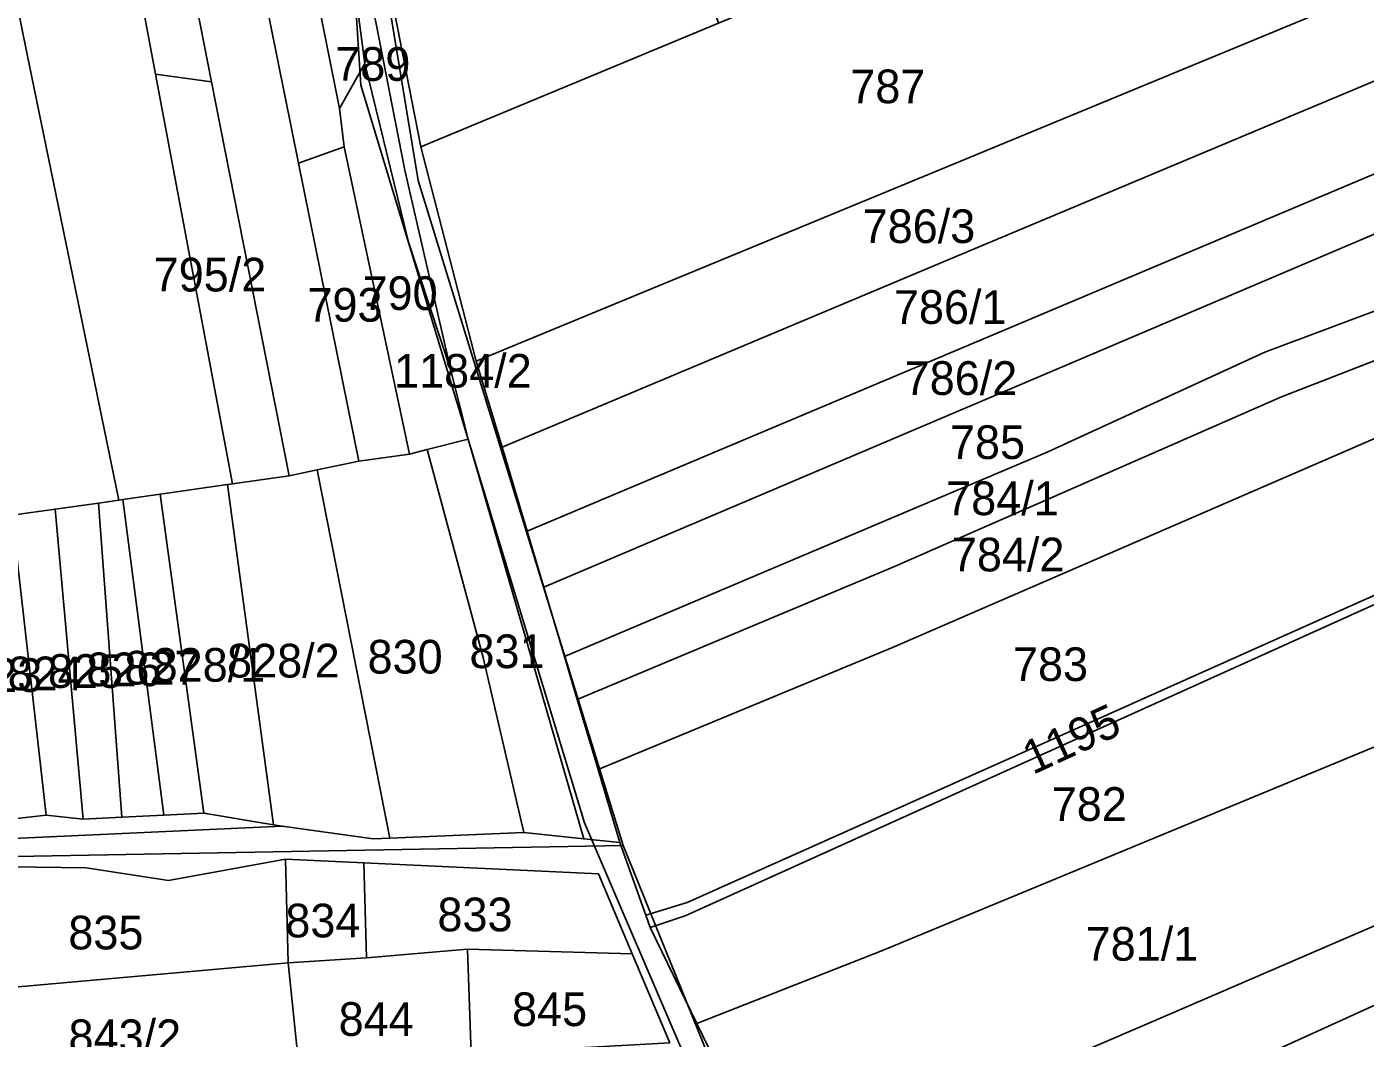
# Model space of a CAD drawing. Extents: x -623250 to -619626, y -1079612 to -1075424.
# Drawn here: x -621038.1 to -620640.4, y -1077296.6 to -1076996.3 of the extents above; entities that cross this region are included whole.
import ezdxf

# ---------------------------------------------------------------- set-up
doc = ezdxf.new("R2010")
doc.units = 0
for name, color, linetype in [('Cestní síť', 7, 'Continuous'), ('Parcela nároku', 7, 'Continuous'), ('Parcelní číslo', 7, 'Continuous'), ('Vodní toky', 7, 'Continuous')]:
    doc.layers.add(name, color=color, linetype=linetype)

msp = doc.modelspace()

# ---------------------------------------------------------------- linework, layer by layer
at = {"layer": 'Cestní síť'}
for p, q in [((-620921.78, -1077041.94), (-620941.41, -1076923.5)), ((-620860.93, -1077239.33), (-620921.78, -1077041.94)), ((-620860.93, -1077239.33), (-621214.45, -1077245.82)), ((-620817.17, -1077347.1), (-620860.93, -1077239.33))]:
    msp.add_line(p, q, dxfattribs=at)
at = {"layer": 'Parcela nároku'}
for points in [[(-620972.42, -1076884.35), (-620988.51, -1076803.88), (-621002.65, -1076813.04), (-620979.97, -1076924.9), (-620957.34, -1077036.71), (-620943.82, -1077031.86), (-620945.19, -1077020.56)], [(-620939.41, -1077125.24), (-620957.34, -1077036.71), (-620979.97, -1076924.9), (-621002.65, -1076813.04), (-621020.06, -1076825.27), (-620983.2, -1077012.58), (-620960.16, -1077129.62), (-620951.82, -1077127.86)], [(-621032.81, -1076834.22), (-621020.06, -1076825.27), (-620983.2, -1077012.58), (-620999.81, -1077010.33)], [(-621040.87, -1076839.88), (-621032.81, -1076834.22), (-620999.81, -1077010.33), (-620977.01, -1077132.01), (-620978.48, -1077132.22), (-620998.5, -1077135.06), (-621009.6, -1077136.64), (-621010.77, -1077136.81), (-621038.05, -1077003.98), (-621065.15, -1076871.1)], [(-621065.15, -1076871.1), (-621038.05, -1077003.98), (-621010.77, -1077136.81), (-621016.81, -1077137.67), (-621029.67, -1077139.5), (-621042.47, -1077141.32), (-621054.91, -1077143.09), (-621078.91, -1077021.62), (-621102.95, -1076900.09), (-621076.1, -1076880.89)], [(-620945.17, -1076884.69), (-620944.66, -1076880.6), (-620940.19, -1076870.41), (-620938.3, -1076883.42), (-620943.44, -1076948.79), (-620925.77, -1077038.84), (-620912.07, -1077098.28), (-620924.65, -1077060.22), (-620937.66, -1077007.21), (-620944.07, -1076958.4), (-620947.15, -1076948.49), (-620946.76, -1076928.27), (-620947.86, -1076911.3)], [(-620951.9, -1076932.96), (-620947.15, -1076948.49), (-620944.07, -1076958.4), (-620937.66, -1077007.21), (-620945.19, -1077020.56), (-620972.42, -1076884.35), (-620950.76, -1076884.62), (-620953.69, -1076914.5)], [(-620860.19, -1076914.89), (-620832.54, -1076995.23), (-620921.02, -1077031.86), (-620937.66, -1076946.83), (-620887.44, -1076925.53)], [(-620629.28, -1076981.86), (-620643.85, -1076916.74), (-620738.29, -1076956.01), (-620832.54, -1076995.23), (-620921.02, -1077031.86), (-620904.58, -1077095.56), (-620767.08, -1077038.8)], [(-620767.08, -1077038.8), (-620904.58, -1077095.56), (-620896.8, -1077121.07), (-620760.56, -1077063.88), (-620624.13, -1077006.64), (-620629.28, -1076981.86)], [(-620999.81, -1077010.33), (-620983.2, -1077012.58), (-620960.16, -1077129.62), (-620977.01, -1077132.01)], [(-620912.07, -1077098.28), (-620924.65, -1077060.22), (-620937.66, -1077007.21), (-620945.19, -1077020.56), (-620943.82, -1077031.86), (-620924.38, -1077123.14), (-620919.18, -1077121.81), (-620906.95, -1077118.69)], [(-620618.82, -1077032.03), (-620624.13, -1077006.64), (-620760.56, -1077063.88), (-620896.8, -1077121.07), (-620889.38, -1077146.03), (-620754.08, -1077089.06)], [(-620943.82, -1077031.86), (-620957.34, -1077036.71), (-620939.41, -1077125.24), (-620924.38, -1077123.14)], [(-620754.08, -1077089.06), (-620618.82, -1077032.03), (-620615.34, -1077048.34), (-620749.99, -1077105.51), (-620884.45, -1077162.62), (-620889.38, -1077146.03)], [(-620749.99, -1077105.51), (-620615.34, -1077048.34), (-620610.74, -1077070.63), (-620670.29, -1077092.89), (-620734.88, -1077122.56), (-620878.33, -1077183.21), (-620884.45, -1077162.62)], [(-620670.29, -1077092.89), (-620734.88, -1077122.56), (-620878.33, -1077183.21), (-620874.52, -1077196.05), (-620780.25, -1077156.48), (-620665.33, -1077106.16), (-620607.96, -1077083.92), (-620610.74, -1077070.63)], [(-620665.33, -1077106.16), (-620607.96, -1077083.92), (-620603.79, -1077103.85), (-620780.87, -1077180.56), (-620868.37, -1077216.75), (-620874.52, -1077196.05), (-620780.25, -1077156.48)], [(-620603.79, -1077103.85), (-620780.87, -1077180.56), (-620868.37, -1077216.75), (-620861.9, -1077238.51), (-620854.18, -1077260.06), (-620841.88, -1077256.29), (-620720.81, -1077202.26), (-620599.73, -1077148.14)], [(-620906.95, -1077118.69), (-620872.61, -1077237.42), (-620890.39, -1077235.55), (-620902.5, -1077183.58), (-620919.18, -1077121.81)], [(-620951.82, -1077127.86), (-620939.41, -1077125.24), (-620924.38, -1077123.14), (-620919.18, -1077121.81), (-620902.5, -1077183.58), (-620890.39, -1077235.55), (-620930.21, -1077237.15)], [(-620978.48, -1077132.22), (-620977.01, -1077132.01), (-620960.16, -1077129.62), (-620951.82, -1077127.86), (-620930.21, -1077237.15), (-620935.21, -1077237.35), (-620962.22, -1077233.64), (-620964.79, -1077233.21)], [(-620978.48, -1077132.22), (-620964.79, -1077233.21), (-620985.48, -1077229.75), (-620998.5, -1077135.06)], [(-621016.81, -1077137.67), (-621010.77, -1077136.81), (-621009.6, -1077136.64), (-620997.36, -1077230.34), (-621009.82, -1077230.96)], [(-621009.6, -1077136.64), (-620998.5, -1077135.06), (-620985.48, -1077229.75), (-620997.36, -1077230.34)], [(-621032.37, -1077230.4), (-621042.47, -1077141.32), (-621054.91, -1077143.09), (-621044.66, -1077231.77)], [(-621021.32, -1077231.53), (-621029.67, -1077139.5), (-621042.47, -1077141.32), (-621032.37, -1077230.4)], [(-621029.67, -1077139.5), (-621016.81, -1077137.67), (-621009.82, -1077230.96), (-621021.32, -1077231.53)], [(-620854.18, -1077260.06), (-620841.88, -1077256.29), (-620720.81, -1077202.26), (-620599.73, -1077148.14), (-620597.96, -1077153.14), (-620616.17, -1077158.13), (-620729.34, -1077209.18), (-620842.44, -1077260.29), (-620852.88, -1077263.68)], [(-620729.34, -1077209.18), (-620842.44, -1077260.29), (-620852.88, -1077263.68), (-620839.03, -1077292.21), (-620783.8, -1077270.52), (-620686.15, -1077230.15), (-620588.31, -1077189.72), (-620593.55, -1077165.29), (-620597.96, -1077153.14), (-620616.17, -1077158.13)], [(-620686.15, -1077230.15), (-620783.8, -1077270.52), (-620839.03, -1077292.21), (-620824.5, -1077322.12), (-620818.03, -1077340.86), (-620698.27, -1077289.33), (-620578.2, -1077237.62), (-620588.31, -1077189.72)], [(-621166.67, -1077233.21), (-621156.36, -1077231.82), (-621144.12, -1077230.17), (-621129.77, -1077230.27), (-621116.92, -1077228.86), (-621105.4, -1077230.88), (-621067.47, -1077233.41), (-621055.85, -1077230.4), (-621044.66, -1077231.77), (-621032.37, -1077230.4), (-621021.32, -1077231.53), (-621009.82, -1077230.96), (-620997.36, -1077230.34), (-620985.48, -1077229.75), (-620964.79, -1077233.21), (-620962.22, -1077233.64), (-621085.4, -1077239.27), (-621216.53, -1077243.73), (-621220.15, -1077236.58), (-621210.93, -1077235.6), (-621181.64, -1077232.5)], [(-620698.27, -1077289.33), (-620578.2, -1077237.62), (-620573.82, -1077257.79), (-620688.76, -1077310.04), (-620812.33, -1077364.99), (-620818.03, -1077340.86)], [(-620995.94, -1077249.72), (-621020.46, -1077245.96), (-621072.57, -1077245.28), (-621061.68, -1077274.39), (-621059.63, -1077283.02), (-620960.48, -1077274.17), (-620961.21, -1077243.43)], [(-620937.95, -1077244.51), (-620937.13, -1077272.7), (-620960.48, -1077274.17), (-620961.21, -1077243.43)], [(-620858.19, -1077271.52), (-620868.27, -1077247.75), (-620937.95, -1077244.51), (-620937.13, -1077272.7), (-620907.16, -1077270.11)], [(-620564.8, -1077306.77), (-620573.82, -1077257.79), (-620688.76, -1077310.04), (-620812.33, -1077364.99), (-620813.72, -1077378.79), (-620674.53, -1077339)], [(-620937.13, -1077272.7), (-620907.16, -1077270.11), (-620906.02, -1077301.21), (-620957.12, -1077305.77), (-620960.48, -1077274.17)], [(-620846.99, -1077297.92), (-620858.19, -1077271.52), (-620907.16, -1077270.11), (-620906.02, -1077301.21)], [(-620960.48, -1077274.17), (-620957.12, -1077305.77), (-620974.2, -1077305.88), (-620976.64, -1077305.9), (-621034.08, -1077311.92), (-621045.83, -1077293.38), (-621058.93, -1077294.62), (-621059.63, -1077283.02)]]:
    msp.add_lwpolyline(points, close=True, dxfattribs=at)
for points in [[(-620937.66, -1076946.83), (-620921.02, -1077031.86), (-620904.58, -1077095.56), (-620896.8, -1077121.07), (-620889.38, -1077146.03), (-620884.45, -1077162.62), (-620878.33, -1077183.21), (-620874.52, -1077196.05), (-620868.37, -1077216.75), (-620861.9, -1077238.51), (-620872.61, -1077237.42), (-620906.95, -1077118.69), (-620912.07, -1077098.28), (-620925.77, -1077038.84), (-620943.44, -1076948.79)], [(-621085.4, -1077239.27), (-620962.22, -1077233.64), (-620935.21, -1077237.35), (-620930.21, -1077237.15), (-620890.39, -1077235.55), (-620872.61, -1077237.42), (-620861.9, -1077238.51), (-620854.18, -1077260.06), (-620852.88, -1077263.68), (-620839.03, -1077292.21), (-620824.5, -1077322.12)], [(-620846.99, -1077297.92), (-620858.19, -1077271.52), (-620868.27, -1077247.75), (-620937.95, -1077244.51), (-620961.21, -1077243.43), (-620995.94, -1077249.72), (-621020.46, -1077245.96), (-621072.57, -1077245.28)]]:
    msp.add_lwpolyline(points, dxfattribs=at)
at = {"layer": 'Vodní toky'}
for p, q in [((-620938.8, -1077013.58), (-620945.97, -1076901.34)), ((-620903.15, -1077131.23), (-620938.8, -1077013.58)), ((-620872.43, -1077232.6), (-620903.15, -1077131.23)), ((-620826.67, -1077339.21), (-620872.43, -1077232.6))]:
    msp.add_line(p, q, dxfattribs=at)

# ---------------------------------------------------------------- texts
at = {"layer": 'Parcelní číslo'}
for s, p in [('789', (-620946.44, -1077012.31)), ('787', (-620793.41, -1077018.96)), ('786/3', (-620789.75, -1077060.48)), ('795/2', (-621000.4, -1077074.85)), ('793', (-620954.71, -1077083.82)), ('790', (-620938.33, -1077080.35)), ('786/1', (-620780.47, -1077084.47)), ('1184/2', (-620928.97, -1077103.42)), ('786/2', (-620777.26, -1077105.57)), ('785', (-620763.81, -1077124.6)), ('784/1', (-620764.94, -1077141.28)), ('784/2', (-620763.24, -1077157.97)), ('831', (-620906.57, -1077186.7)), ('828/1', (-621000.71, -1077190.73)), ('828/2', (-620978.58, -1077189.48)), ('830', (-620936.85, -1077188.31)), ('783', (-620745.09, -1077190.53)), ('823', (-621055.79, -1077193.76)), ('824', (-621043.77, -1077193.27)), ('825', (-621031.78, -1077192.56)), ('826', (-621020.38, -1077192.06)), ('827', (-621009.09, -1077191.56)), ('782', (-620733.56, -1077232.05)), ('834', (-620961.27, -1077266.65)), ('833', (-620916.08, -1077264.84)), ('835', (-621025.75, -1077270.22)), ('781/1', (-620723.49, -1077273.56)), ('845', (-620893.92, -1077292.99)), ('844', (-620945.43, -1077295.89)), ('843/2', (-621025.7, -1077301.02))]:
    msp.add_text(s, height=10, dxfattribs=at).set_placement(p)
msp.add_text('1195', height=10, rotation=24.8081, dxfattribs=at).set_placement((-620739.2, -1077218.48))

doc.saveas('drawing.dxf')
